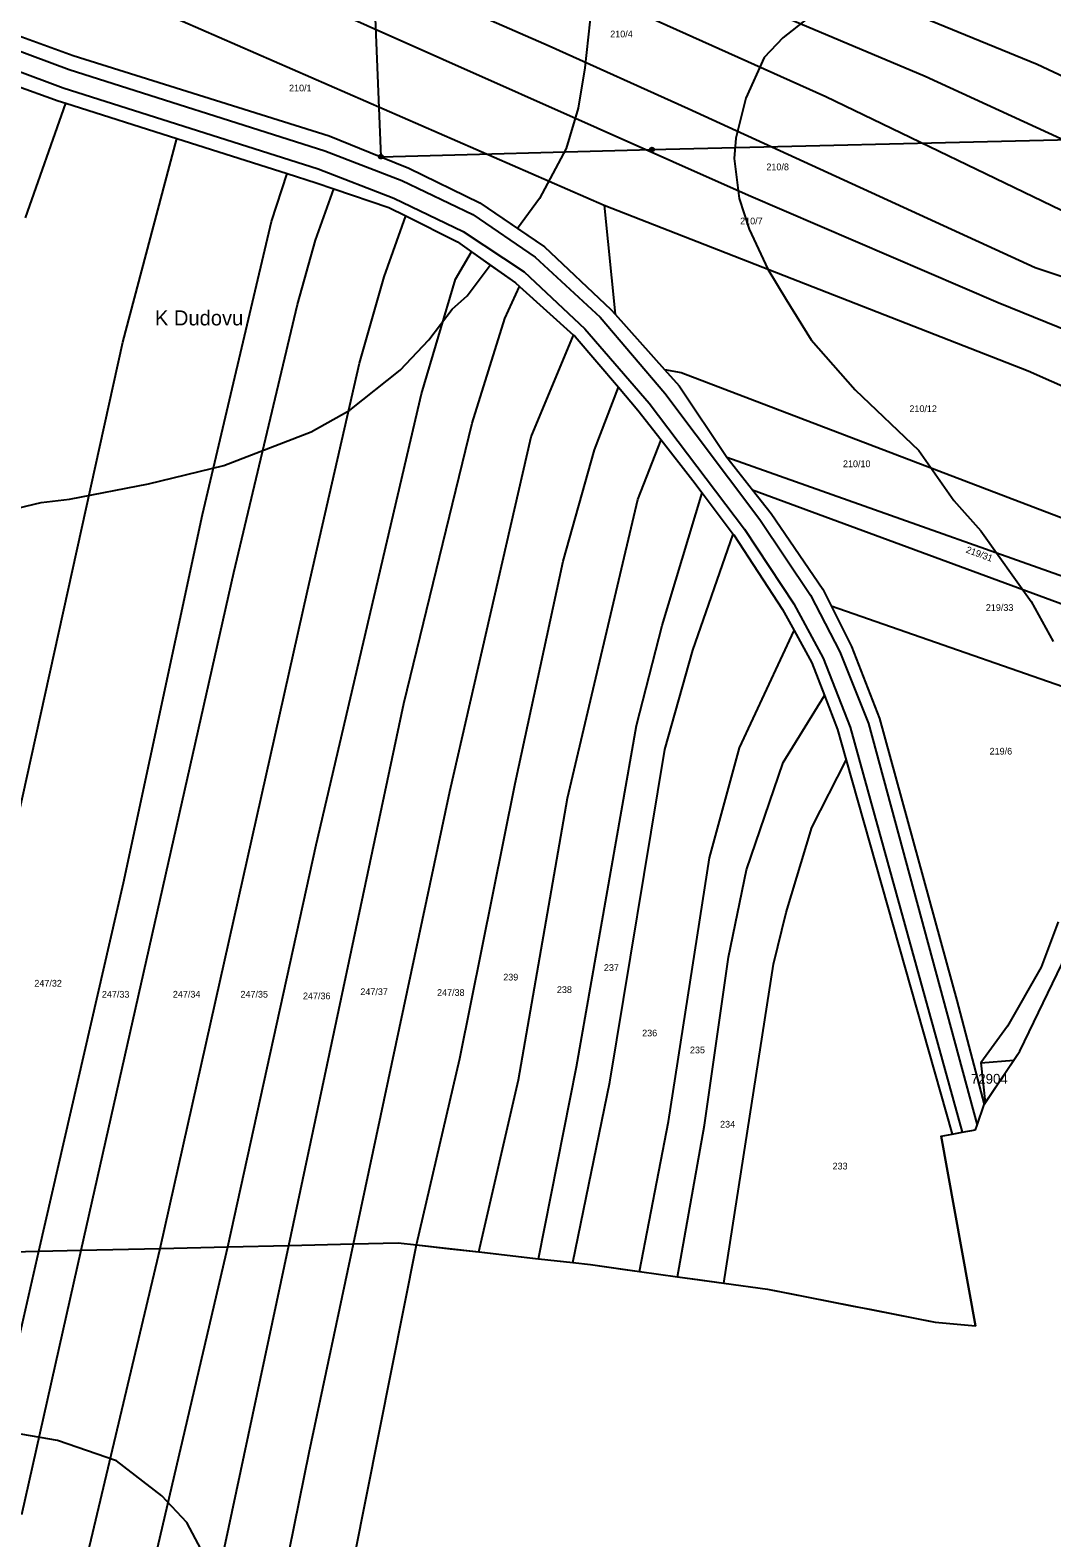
# Model space of a CAD drawing. Extents: x -743888 to -742027, y -1128394 to -1126768.
# Drawn here: x -742978.3 to -742720.1, y -1128170.4 to -1127789.2 of the extents above; entities that cross this region are included whole.
import ezdxf

# ---------------------------------------------------------------- set-up
doc = ezdxf.new("R2010")
doc.units = 0
for name, color, linetype in [('Vrstva 1', 7, 'Continuous'), ('Vrstva 12', 7, 'Continuous'), ('Vrstva 13', 7, 'Continuous'), ('Vrstva 15', 7, 'Continuous'), ('Vrstva 18', 7, 'Continuous'), ('Vrstva 26', 7, 'Continuous'), ('Vrstva 4', 7, 'Continuous'), ('Vrstva 52', 7, 'Continuous'), ('Vrstva 53', 7, 'Continuous'), ('Vrstva 6', 7, 'Continuous')]:
    doc.layers.add(name, color=color, linetype=linetype)

msp = doc.modelspace()

# ---------------------------------------------------------------- linework, layer by layer
at = {"layer": 'Vrstva 1'}
for points in [[(-742991.64, -1127786.82), (-742967.48, -1127795.61)], [(-742967.48, -1127795.61), (-742902.77, -1127815.89)], [(-742982.41, -1127802.98), (-742971.25, -1127807.04)], [(-742971.25, -1127807.04), (-742969.31, -1127807.66)], [(-742969.31, -1127807.66), (-742941.27, -1127816.58)], [(-742941.27, -1127816.58), (-742913.36, -1127825.45)], [(-742902.77, -1127815.89), (-742889.66, -1127821.18)], [(-742889.66, -1127821.18), (-742882.56, -1127824.07)], [(-742882.56, -1127824.07), (-742864.61, -1127832.85)], [(-742913.36, -1127825.45), (-742905.98, -1127827.8)], [(-742905.98, -1127827.8), (-742901.58, -1127829.29)], [(-742901.58, -1127829.29), (-742887.63, -1127833.99)], [(-742887.63, -1127833.99), (-742883.39, -1127836.13)], [(-742883.39, -1127836.13), (-742870.31, -1127842.73)], [(-742864.61, -1127832.85), (-742848.33, -1127844.01)], [(-742870.31, -1127842.73), (-742866.75, -1127845.26)], [(-742848.33, -1127844.01), (-742831.55, -1127859.78)], [(-742866.75, -1127845.26), (-742855.66, -1127853.11)], [(-742855.66, -1127853.11), (-742854.64, -1127854.03)], [(-742854.64, -1127854.03), (-742840.94, -1127866.29)], [(-742831.55, -1127859.78), (-742830.43, -1127861.03)], [(-742830.43, -1127861.03), (-742817.94, -1127875.01)], [(-742840.94, -1127866.29), (-742840.54, -1127866.65)], [(-742840.54, -1127866.65), (-742829.62, -1127879.49)], [(-742817.94, -1127875.01), (-742814.27, -1127879.12)], [(-742829.62, -1127879.49), (-742824.72, -1127885.25)], [(-742814.27, -1127879.12), (-742802.25, -1127897.14)], [(-742824.72, -1127885.25), (-742818.84, -1127892.78)], [(-742818.84, -1127892.78), (-742810.82, -1127903.05)], [(-742802.25, -1127897.14), (-742686.17, -1127938.31)], [(-742802.25, -1127897.14), (-742795.76, -1127905.39)], [(-742810.82, -1127903.05), (-742808.46, -1127906.18)], [(-742808.46, -1127906.18), (-742800.6, -1127916.58)], [(-742795.76, -1127905.39), (-742791.02, -1127911.43)], [(-742791.02, -1127911.43), (-742777.97, -1127930.5)], [(-742800.6, -1127916.58), (-742800.46, -1127916.77)], [(-742800.46, -1127916.77), (-742788.13, -1127935.67)], [(-742777.97, -1127930.5), (-742775.86, -1127934.72)], [(-742788.13, -1127935.67), (-742785.19, -1127941)], [(-742775.86, -1127934.72), (-742770.7, -1127945.05)], [(-742785.19, -1127941), (-742780.69, -1127949.15)], [(-742770.7, -1127945.05), (-742763.59, -1127963.24)], [(-742780.69, -1127949.15), (-742777.55, -1127957.37)], [(-742777.55, -1127957.37), (-742774.23, -1127966.04)], [(-742774.23, -1127966.04), (-742772.05, -1127973.74)], [(-742763.59, -1127963.24), (-742744.12, -1128034.5)], [(-742772.05, -1127973.74), (-742745.25, -1128068.29)], [(-742744.12, -1128034.5), (-742737.18, -1128060.8)], [(-742896.59, -1128096.06), (-742885.31, -1128095.8)], [(-742885.31, -1128095.8), (-742880.65, -1128096.32)], [(-743006.9, -1128098.63), (-742976.11, -1128097.91)], [(-742976.11, -1128097.91), (-742965.39, -1128097.66)], [(-742965.39, -1128097.66), (-742945.48, -1128097.2)], [(-742945.48, -1128097.2), (-742928.33, -1128096.8)], [(-742928.33, -1128096.8), (-742912.92, -1128096.44)], [(-742912.92, -1128096.44), (-742896.59, -1128096.06)]]:
    msp.add_lwpolyline(points, dxfattribs=at)
at = {"layer": 'Vrstva 12'}
for points in [[(-742892.25, -1127757.26), (-742889.66, -1127821.18)], [(-742821.14, -1127819.37), (-742715.13, -1127816.8)], [(-742889.66, -1127821.18), (-742821.14, -1127819.37)]]:
    msp.add_lwpolyline(points, dxfattribs=at)
at = {"layer": 'Vrstva 13'}
for p, q in [((-742728.18, -1128047.33), (-742716.39, -1128022.92)), ((-742748.02, -1128068.81), (-742739.36, -1128116.8))]:
    msp.add_line(p, q, dxfattribs=at)
for points in [[(-742737.18, -1128060.8), (-742729.28, -1128048.97)], [(-742729.28, -1128048.97), (-742728.18, -1128047.33)], [(-742738.98, -1128066.02), (-742737.18, -1128060.8)], [(-742748.02, -1128068.81), (-742745.25, -1128068.29)], [(-742745.25, -1128068.29), (-742742.76, -1128067.85)], [(-742742.76, -1128067.85), (-742739.4, -1128067.25)], [(-742739.4, -1128067.25), (-742738.98, -1128066.02)], [(-742899.56, -1128191.16), (-742880.65, -1128096.32)], [(-742880.65, -1128096.32), (-742872.14, -1128097.28)], [(-742872.14, -1128097.28), (-742864.87, -1128098.1)], [(-742864.87, -1128098.1), (-742863.41, -1128098.26)], [(-742863.41, -1128098.26), (-742851.3, -1128099.63)], [(-742851.3, -1128099.63), (-742849.78, -1128099.8)], [(-742849.78, -1128099.8), (-742845.11, -1128100.32)], [(-742845.11, -1128100.32), (-742841.14, -1128100.77)], [(-742841.14, -1128100.77), (-742836.67, -1128101.27)], [(-742836.67, -1128101.27), (-742827.97, -1128102.49)], [(-742827.97, -1128102.49), (-742824.28, -1128103)], [(-742824.28, -1128103), (-742814.65, -1128104.35)], [(-742814.65, -1128104.35), (-742809.56, -1128105.06)], [(-742809.56, -1128105.06), (-742802.94, -1128105.99)], [(-742802.94, -1128105.99), (-742791.91, -1128107.53)], [(-742791.91, -1128107.53), (-742785.41, -1128108.8)], [(-742785.41, -1128108.8), (-742770.28, -1128111.77)], [(-742770.28, -1128111.77), (-742766.05, -1128112.6)], [(-742766.05, -1128112.6), (-742756.81, -1128114.41)], [(-742756.81, -1128114.41), (-742751.78, -1128115.4)], [(-742751.78, -1128115.4), (-742749.59, -1128115.83)], [(-742749.59, -1128115.83), (-742739.36, -1128116.8)]]:
    msp.add_lwpolyline(points, dxfattribs=at)
at = {"layer": 'Vrstva 26'}
for p, q in [((-742890.12, -1127821.36), (-742889.47, -1127820.72)), ((-742889.86, -1127821.63), (-742889.21, -1127820.98)), ((-742821.6, -1127819.55), (-742820.95, -1127818.91)), ((-742821.34, -1127819.82), (-742820.69, -1127819.17))]:
    msp.add_line(p, q, dxfattribs=at)
for centre in [(-742889.66, -1127821.18), (-742821.14, -1127819.37)]:
    msp.add_circle(centre, 0.5, dxfattribs=at)
at = {"layer": 'Vrstva 4'}
for points in [[(-742992.69, -1127790.12), (-742968.49, -1127799.16)], [(-742994.83, -1127794.53), (-742969.96, -1127803.78)], [(-742968.49, -1127799.16), (-742903.86, -1127819.67)], [(-742969.96, -1127803.78), (-742905.49, -1127824.29)], [(-742903.86, -1127819.67), (-742884.37, -1127827.16)], [(-742905.49, -1127824.29), (-742886.43, -1127831.69)], [(-742884.37, -1127827.16), (-742866.45, -1127835.83)], [(-742886.43, -1127831.69), (-742868.83, -1127840.11)], [(-742866.45, -1127835.83), (-742850.65, -1127846.58)], [(-742868.83, -1127840.11), (-742853.46, -1127850.3)], [(-742850.65, -1127846.58), (-742834.26, -1127861.78)], [(-742853.46, -1127850.3), (-742838.11, -1127864.73)], [(-742834.26, -1127861.78), (-742817.86, -1127880.99)], [(-742838.11, -1127864.73), (-742821.82, -1127883.53)], [(-742817.86, -1127880.99), (-742793.88, -1127912.91)], [(-742821.82, -1127883.53), (-742797.76, -1127915.33)], [(-742797.76, -1127915.33), (-742785.31, -1127934.27)], [(-742793.88, -1127912.91), (-742781.08, -1127932.06)], [(-742785.31, -1127934.27), (-742777.87, -1127947.95)], [(-742781.08, -1127932.06), (-742773.68, -1127946.37)], [(-742773.68, -1127946.37), (-742766.43, -1127964.48)], [(-742777.87, -1127947.95), (-742771.04, -1127965.41)], [(-742771.04, -1127965.41), (-742742.76, -1128067.85)], [(-742766.43, -1127964.48), (-742738.98, -1128066.02)]]:
    msp.add_lwpolyline(points, dxfattribs=at)
at = {"layer": 'Vrstva 52'}
for points in [[(-743053.67, -1127722.32), (-743053.72, -1127722.94), (-743049.21, -1127739.41), (-743048.14, -1127743.3), (-743040.35, -1127758.3), (-743030.5, -1127771.33), (-743025.38, -1127776.65), (-743015.05, -1127787.39), (-743011.33, -1127789.48), (-742996.28, -1127797.93), (-742982.41, -1127802.98), (-742971.25, -1127807.04), (-742969.31, -1127807.66), (-742941.27, -1127816.58), (-742913.36, -1127825.45), (-742905.98, -1127827.8), (-742901.58, -1127829.29), (-742887.63, -1127833.99), (-742883.39, -1127836.13), (-742870.31, -1127842.73), (-742866.75, -1127845.26), (-742862.04, -1127848.59)], [(-743039.23, -1127734.18), (-743030.31, -1127741.5), (-743008.69, -1127756.75), (-742998.94, -1127762.63), (-742981.5, -1127764.75), (-742969.25, -1127763.5), (-742946.75, -1127755), (-742935.69, -1127749.13), (-742914.06, -1127739.38), (-742905.56, -1127736.38), (-742887.75, -1127733), (-742875.44, -1127732.5), (-742855.5, -1127738.88), (-742848.75, -1127745.25), (-742840.69, -1127757.63), (-742837.69, -1127765.63), (-742836, -1127779.25), (-742838.13, -1127798.75), (-742839.81, -1127808.88), (-742842.81, -1127819.13), (-742849.56, -1127831.75), (-742855.17, -1127839.32)], [(-743039.23, -1127734.18), (-743037.36, -1127739.74), (-743036.47, -1127741.45), (-743030.16, -1127753.57), (-743021.89, -1127765.25), (-743006.65, -1127779.24), (-742997.92, -1127784.13), (-742991.64, -1127786.82), (-742967.48, -1127795.61), (-742902.77, -1127815.89), (-742889.66, -1127821.18), (-742882.56, -1127824.07), (-742864.61, -1127832.85), (-742855.17, -1127839.32)], [(-742776.63, -1127782.13), (-742788.06, -1127791.13), (-742792.75, -1127796.13), (-742797.44, -1127806.38), (-742799.94, -1127816.5), (-742800.38, -1127821.63), (-742799.13, -1127831.75), (-742796.56, -1127839.5), (-742791.88, -1127849.63), (-742787.25, -1127857.25), (-742780.88, -1127867.5), (-742769.81, -1127880.13), (-742753.69, -1127895.5), (-742744.81, -1127908.13), (-742738, -1127915.75), (-742725.31, -1127933.63), (-742719.75, -1127943.75)], [(-742855.17, -1127839.32), (-742848.33, -1127844.01), (-742831.55, -1127859.78), (-742830.43, -1127861.03), (-742817.94, -1127875.01), (-742814.27, -1127879.12), (-742802.25, -1127897.14), (-742795.76, -1127905.39), (-742791.02, -1127911.43), (-742777.97, -1127930.5), (-742775.86, -1127934.72), (-742770.7, -1127945.05), (-742763.59, -1127963.24), (-742744.12, -1128034.5), (-742737.18, -1128060.8)], [(-743002.31, -1127915), (-742975.56, -1127908.63), (-742968.38, -1127907.75), (-742948.44, -1127903.88), (-742929.38, -1127899.25), (-742907.31, -1127890.75), (-742897.5, -1127885.25), (-742884.81, -1127875.13), (-742877.56, -1127867.5), (-742871.63, -1127859.75), (-742867.81, -1127856.38), (-742862.04, -1127848.59)], [(-742862.04, -1127848.59), (-742855.66, -1127853.11), (-742854.64, -1127854.03), (-742840.94, -1127866.29), (-742840.54, -1127866.65), (-742829.62, -1127879.49), (-742824.72, -1127885.25), (-742818.84, -1127892.78), (-742810.82, -1127903.05), (-742808.46, -1127906.18), (-742800.6, -1127916.58), (-742800.46, -1127916.77), (-742788.13, -1127935.67), (-742785.19, -1127941), (-742780.69, -1127949.15), (-742777.55, -1127957.37), (-742774.23, -1127966.04), (-742772.05, -1127973.74), (-742745.25, -1128068.29)], [(-742729.71, -1128049.62), (-742728.18, -1128047.33), (-742716.39, -1128022.92), (-742711.15, -1128012.08), (-742710.24, -1128010.19), (-742707.81, -1128007.87), (-742683.48, -1127999.26)], [(-742718.5, -1128014.63), (-742722.75, -1128026.13), (-742731.25, -1128041), (-742738, -1128050.25)], [(-742738, -1128050.25), (-742729.71, -1128049.62)], [(-742736.88, -1128060.35), (-742729.71, -1128049.62)], [(-742738, -1128050.25), (-742736.88, -1128060.35)], [(-742737.18, -1128060.8), (-742736.88, -1128060.35)], [(-742971.68, -1128360.06), (-742964.35, -1128361.25), (-742947.57, -1128363.98), (-742918.75, -1128266.43), (-742899.56, -1128191.16), (-742880.65, -1128096.32), (-742864.87, -1128098.1), (-742849.78, -1128099.8), (-742841.14, -1128100.77), (-742836.67, -1128101.27), (-742824.28, -1128103), (-742814.65, -1128104.35), (-742802.94, -1128105.99), (-742791.91, -1128107.53), (-742749.59, -1128115.83), (-742739.36, -1128116.8), (-742748.02, -1128068.81), (-742745.25, -1128068.29)], [(-742971.68, -1128360.06), (-742965.81, -1128355.38), (-742953.5, -1128342.63), (-742949.31, -1128335), (-742943.38, -1128319.63), (-742932.75, -1128294.25), (-742922.56, -1128259), (-742921.31, -1128242.88), (-742921.31, -1128231), (-742922.13, -1128225.88), (-742922.13, -1128218.25), (-742925.94, -1128197.88), (-742931.44, -1128180.13), (-742938.69, -1128166.5), (-742945.06, -1128159.75), (-742956.5, -1128150.88), (-742971.38, -1128145.75), (-742996.38, -1128141.5)]]:
    msp.add_lwpolyline(points, dxfattribs=at)
at = {"layer": 'Vrstva 6'}
for points in [[(-742855.88, -1127756.96), (-742752.11, -1127800.85)], [(-742921.78, -1127760.46), (-742847.12, -1127793.15)], [(-742972.27, -1127772.64), (-742833.19, -1127833.4)], [(-742779.52, -1127774.85), (-742723.74, -1127797.75)], [(-742912.22, -1127779.41), (-742796.71, -1127830.89)], [(-742839.56, -1127777.92), (-742777.16, -1127805.95)], [(-742847.12, -1127793.15), (-742812.02, -1127809)], [(-742723.74, -1127797.75), (-742697.57, -1127810.08)], [(-742752.11, -1127800.85), (-742705.33, -1127822.31)], [(-742777.16, -1127805.95), (-742712.92, -1127837.01)], [(-742979.49, -1127836.62), (-742969.31, -1127807.66)], [(-742812.02, -1127809), (-742724.3, -1127849.19)], [(-742954.92, -1127868.05), (-742941.27, -1127816.58)], [(-742917.32, -1127837.6), (-742913.36, -1127825.45)], [(-742906.15, -1127842.32), (-742901.58, -1127829.29)], [(-742796.71, -1127830.89), (-742733.59, -1127858.01)], [(-742888.84, -1127851.53), (-742883.39, -1127836.13)], [(-742833.19, -1127833.4), (-742726.08, -1127875.32)], [(-742833.19, -1127833.4), (-742830.43, -1127861.03)], [(-742934.78, -1127911.65), (-742917.32, -1127837.6)], [(-742910.73, -1127858.59), (-742906.15, -1127842.32)], [(-742870.77, -1127852.17), (-742866.75, -1127845.26)], [(-742895.08, -1127873.37), (-742888.84, -1127851.53)], [(-742724.3, -1127849.19), (-742701.43, -1127856.81)], [(-742879.36, -1127881.1), (-742870.77, -1127852.17)], [(-742858.3, -1127862.06), (-742854.64, -1127854.03)], [(-742926.85, -1127926.34), (-742910.73, -1127858.59)], [(-742733.59, -1127858.01), (-742670.28, -1127883.77)], [(-742866.58, -1127888.59), (-742858.3, -1127862.06)], [(-742851.64, -1127891.97), (-742840.94, -1127866.29)], [(-742981.41, -1127988.5), (-742954.92, -1127868.05)], [(-742908.25, -1127930.92), (-742895.08, -1127873.37)], [(-742817.94, -1127875.01), (-742813.75, -1127875.71)], [(-742813.75, -1127875.71), (-742683.5, -1127925.44)], [(-742726.08, -1127875.32), (-742678.13, -1127896.57)], [(-742906.05, -1127995.14), (-742879.36, -1127881.1)], [(-742835.64, -1127895.32), (-742829.62, -1127879.49)], [(-742883.88, -1127959.44), (-742866.58, -1127888.59)], [(-742872.27, -1127981.64), (-742851.64, -1127891.97)], [(-742824.75, -1127907.89), (-742818.84, -1127892.78)], [(-742843.58, -1127923.46), (-742835.64, -1127895.32)], [(-742842.47, -1127983.35), (-742824.75, -1127907.89)], [(-742818.57, -1127939.73), (-742808.46, -1127906.18)], [(-742795.76, -1127905.39), (-742687.4, -1127945.34)], [(-742954.73, -1128004.76), (-742934.78, -1127911.65)], [(-742810.82, -1127945.91), (-742800.6, -1127916.58)], [(-742855.73, -1127979.68), (-742843.58, -1127923.46)], [(-742965.39, -1128097.66), (-742926.85, -1127926.34)], [(-742945.48, -1128097.2), (-742908.25, -1127930.92)], [(-742775.86, -1127934.72), (-742698.39, -1127961.68)], [(-742825.08, -1127964.96), (-742818.57, -1127939.73)], [(-742799.05, -1127970.68), (-742785.19, -1127941)], [(-742817.85, -1127971.05), (-742810.82, -1127945.91)], [(-742787.96, -1127974.34), (-742777.55, -1127957.37)], [(-742912.92, -1128096.44), (-742883.88, -1127959.44)], [(-742840.18, -1128051.28), (-742825.08, -1127964.96)], [(-742831.77, -1128055.15), (-742817.85, -1127971.05)], [(-742806.6, -1127998.43), (-742799.05, -1127970.68)], [(-742780.73, -1127990.76), (-742772.05, -1127973.74)], [(-742797.26, -1128001.5), (-742787.96, -1127974.34)], [(-742869.71, -1128049.18), (-742855.73, -1127979.68)], [(-742896.59, -1128096.06), (-742872.27, -1127981.64)], [(-742854.91, -1128054.54), (-742842.47, -1127983.35)], [(-742787.24, -1128012.25), (-742780.73, -1127990.76)], [(-742928.33, -1128096.8), (-742906.05, -1127995.14)], [(-742816.93, -1128065.15), (-742806.6, -1127998.43)], [(-742801.83, -1128023.54), (-742797.26, -1128001.5)], [(-742976.11, -1128097.91), (-742954.73, -1128004.76)], [(-742790.44, -1128025.37), (-742787.24, -1128012.25)], [(-742807.9, -1128066.04), (-742801.83, -1128023.54)], [(-742802.94, -1128105.99), (-742790.44, -1128025.37)], [(-742880.65, -1128096.32), (-742869.71, -1128049.18)], [(-742849.78, -1128099.8), (-742840.18, -1128051.28)], [(-742864.87, -1128098.1), (-742854.91, -1128054.54)], [(-742841.14, -1128100.77), (-742831.77, -1128055.15)], [(-742824.28, -1128103), (-742816.93, -1128065.15)], [(-742814.65, -1128104.35), (-742807.9, -1128066.04)], [(-742994.72, -1128304.77), (-742945.48, -1128097.2)], [(-742992.2, -1128168.37), (-742976.11, -1128097.91)], [(-742980.43, -1128164.49), (-742965.39, -1128097.66)], [(-742964.57, -1128252.03), (-742928.33, -1128096.8)], [(-742932.22, -1128187.07), (-742912.92, -1128096.44)], [(-742907.81, -1128148.82), (-742896.59, -1128096.06)], [(-742915.26, -1128185.79), (-742907.81, -1128148.82)]]:
    msp.add_lwpolyline(points, dxfattribs=at)

# ---------------------------------------------------------------- texts
at = {"layer": 'Vrstva 15'}
msp.add_text('K Dudovu', height=3.8, dxfattribs=at).set_placement((-742946.77, -1127863.84))
at = {"layer": 'Vrstva 18'}
for s, p in [('210/4', (-742831.69, -1127791.01)), ('210/1', (-742912.87, -1127804.67)), ('210/8', (-742792.21, -1127824.61)), ('210/7', (-742798.85, -1127838.28)), ('210/12', (-742756.07, -1127885.75)), ('210/10', (-742772.86, -1127899.68)), ('219/33', (-742736.74, -1127936.02)), ('219/6', (-742735.79, -1127972.34)), ('237', (-742833.28, -1128027.04)), ('247/32', (-742977.25, -1128031.01)), ('239', (-742858.73, -1128029.46)), ('238', (-742845.17, -1128032.62)), ('247/33', (-742960.18, -1128033.8)), ('247/34', (-742942.24, -1128033.79)), ('247/35', (-742925.16, -1128033.79)), ('247/36', (-742909.36, -1128034.21)), ('247/37', (-742894.85, -1128033.15)), ('247/38', (-742875.46, -1128033.36)), ('236', (-742823.62, -1128043.59)), ('235', (-742811.54, -1128047.87)), ('234', (-742803.92, -1128066.65)), ('233', (-742775.49, -1128077.24))]:
    msp.add_text(s, height=1.7, dxfattribs=at).set_placement(p)
msp.add_text('219/31', height=1.7, rotation=339.8236, dxfattribs=at).set_placement((-742741.92, -1127921.22))
at = {"layer": 'Vrstva 53'}
msp.add_text('72904', height=2.5, dxfattribs=at).set_placement((-742740.51, -1128055.57))

doc.saveas('drawing.dxf')
